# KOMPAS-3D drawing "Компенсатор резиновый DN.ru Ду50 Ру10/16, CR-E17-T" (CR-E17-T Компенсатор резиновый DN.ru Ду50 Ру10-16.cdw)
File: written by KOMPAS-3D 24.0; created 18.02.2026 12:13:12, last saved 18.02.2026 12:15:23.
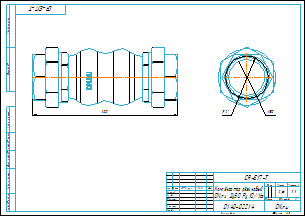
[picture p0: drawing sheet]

Document properties: Типовые: Типовые; Автор: DN.RU; Форматы листов документа: A3; Полное имя файла: CR-E17-T Компенсатор резиновый DN.ru Ду50 Ру10-16.m3d; Масса: 2.6; Наименование: Компенсатор резиновый DN.ru Ду50 Ру10/16; Количество листов документа: 1; Комментарий: D140-02214; Примечание: D140-02214

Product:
- Body: Твердое тело1  | qty 1
    Масса: 2.752084
- Part/product: Компенсатор резиновый DN.ru Ду50 Ру10/16  | designation CR-E17-T
    Масса: 2.6
    Раздел спецификации: Прочие изделия
    Форматы листов документа: A3
    Комментарий: D140-02214
    Примечание: D140-02214
    additional columns: Типовые

Views: Вид 1, Справа, Проекционный вид 2
Referenced files in D:\Работа\Компенсаторы\CR-Е17-T Компенсатор резиновый DN.ru Ду15-80\DN50\: CR-E17-T Компенсатор резиновый DN.ru Ду50 Ру10-16.m3d, CR-E17-T Компенсатор резиновый DN.ru Ду50 Ру10-16.cdw
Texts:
  Линейный размер
  CR-E17-T
  Диаметральный размер
  Компенсатор резиновый
  DN.ru Ду50 Ру10/16
  Твердое тело1
  Компенсатор резиновый DN.ru Ду50 Ру10/16
  CR-E17-T Компенсатор резиновый DN.ru Ду50 Ру10/16
Dimensions and other numbers on the sheet: 0; 3; 2; 4; 200; 50; 1:1; 1; 2,6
